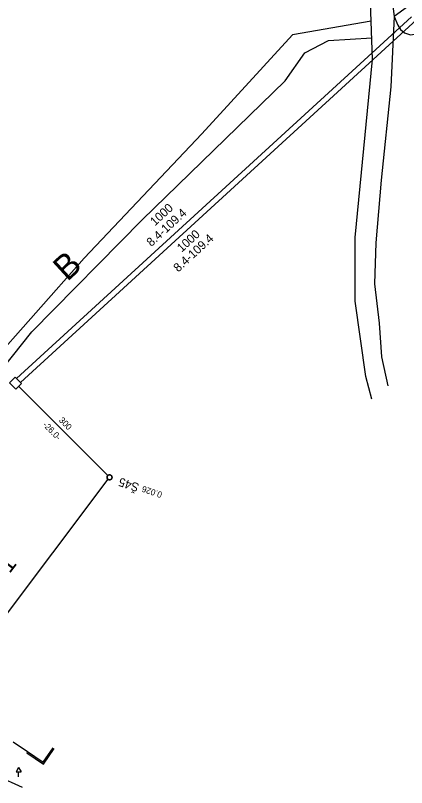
# Model space of a CAD drawing. Extents: x -574526 to -573537, y -1188297 to -1187280.
# Drawn here: x -573818.5 to -573739.4, y -1187727.9 to -1187571.7 of the extents above; entities that cross this region are included whole.
import ezdxf

# ---------------------------------------------------------------- set-up
doc = ezdxf.new("R2010")
doc.units = 0
for name, color, linetype in [('Vrstva 10', 7, 'Continuous'), ('Vrstva 13', 7, 'Continuous'), ('Vrstva 14', 7, 'Continuous'), ('Vrstva 18', 7, 'Continuous'), ('Vrstva 2', 7, 'Continuous'), ('Vrstva 20', 7, 'Continuous'), ('Vrstva 6', 7, 'Continuous'), ('Vrstva 8', 7, 'Continuous'), ('Vrstva 9', 7, 'Continuous')]:
    doc.layers.add(name, color=color, linetype=linetype)

# ---------------------------------------------------------------- blocks, each defined once
blk = doc.blocks.new('5$271')
at = {"layer": 'Vrstva 6'}
for p, q in [((0, 3.732), (-1, 2)), ((0, 3.732), (1, 2)), ((-1, 2), (1, 2)), ((0, 0), (0, 2))]:
    blk.add_line(p, q, dxfattribs=at)

msp = doc.modelspace()

# ---------------------------------------------------------------- linework, layer by layer
at = {"layer": 'Vrstva 10'}
msp.add_lwpolyline([(-573620.8, -1187483.84), (-573741.93, -1187571.94), (-573741.22, -1187573.73), (-573740.64, -1187574.56), (-573739.89, -1187575.23), (-573738.64, -1187575.65), (-573736.64, -1187575.31), (-573616.81, -1187489)], dxfattribs=at)
at = {"layer": 'Vrstva 2'}
for p, q in [((-573818.29, -1187645.17), (-573738.43, -1187572)), ((-573817.49, -1187645.96), (-573737.37, -1187572.55)), ((-573799.82, -1187664.79), (-573817.83, -1187646.74)), ((-573844.19, -1187724.63), (-573799.77, -1187665.54))]:
    msp.add_line(p, q, dxfattribs=at)
at = {"layer": 'Vrstva 20'}
for points in [[(-573795.53, -1187405.69), (-573792.23, -1187408.34), (-573784.28, -1187417.75), (-573780.7, -1187424.87), (-573775.33, -1187439.65), (-573771.1, -1187451.06), (-573764.6, -1187463.55), (-573752.36, -1187503.61), (-573747.53, -1187527.64), (-573741.93, -1187571.94), (-573742.6, -1187586.18), (-573744.6, -1187605.04), (-573745.68, -1187617.7), (-573745.93, -1187626.03), (-573745.01, -1187633.94), (-573744.51, -1187640.77), (-573743.23, -1187646.67)], [(-573746.49, -1187649.33), (-573747.68, -1187644.77), (-573749.84, -1187629.53), (-573749.84, -1187616.62), (-573746.34, -1187580.64), (-573746.59, -1187572.9), (-573747.09, -1187559.66), (-573752.76, -1187522.68), (-573756.77, -1187503.15), (-573764.52, -1187475.21), (-573771.52, -1187459.72), (-573776.68, -1187449.39), (-573786.08, -1187424.04)], [(-573746.59, -1187572.9), (-573762.51, -1187575.67), (-573780.83, -1187595.65), (-573804.57, -1187620.85), (-573824.18, -1187642.92)], [(-573838.44, -1187664.92), (-573815.18, -1187635.73), (-573792.91, -1187613.04), (-573763.97, -1187584.93), (-573760.01, -1187579.31), (-573755.22, -1187576.81), (-573746.49, -1187576.26)]]:
    msp.add_lwpolyline(points, dxfattribs=at)
at = {"layer": 'Vrstva 6'}
for p, q in [((-573818.98, -1187718.61), (-573816.03, -1187720.57)), ((-573816.03, -1187720.57), (-573816.2, -1187720.82)), ((-573816.2, -1187720.82), (-573812.81, -1187723.14)), ((-573816.03, -1187720.57), (-573812.89, -1187722.72)), ((-573812.89, -1187722.72), (-573810.9, -1187719.82)), ((-573812.81, -1187723.14), (-573810.65, -1187719.99))]:
    msp.add_line(p, q, dxfattribs=at)
at = {"layer": 'Vrstva 8'}
for points in [[(-573819.7, -1187646.02), (-573818.4, -1187647.31), (-573817.27, -1187646.17), (-573818.58, -1187644.88), (-573819.7, -1187646.02)], [(-573799.95, -1187665.02), (-573799.96, -1187665.07), (-573799.97, -1187665.12), (-573799.97, -1187665.17), (-573799.96, -1187665.23), (-573799.95, -1187665.28), (-573799.93, -1187665.33), (-573799.91, -1187665.37), (-573799.88, -1187665.42), (-573799.85, -1187665.46), (-573799.82, -1187665.5), (-573799.78, -1187665.53), (-573799.73, -1187665.56), (-573799.69, -1187665.59), (-573799.64, -1187665.61), (-573799.59, -1187665.63), (-573799.54, -1187665.64), (-573799.49, -1187665.64), (-573799.43, -1187665.64), (-573799.38, -1187665.64), (-573799.33, -1187665.62), (-573799.28, -1187665.61), (-573799.23, -1187665.58), (-573799.19, -1187665.56), (-573799.15, -1187665.53), (-573799.11, -1187665.49), (-573799.07, -1187665.45), (-573799.04, -1187665.41), (-573799.02, -1187665.36), (-573799, -1187665.32), (-573798.98, -1187665.27), (-573798.97, -1187665.21), (-573798.97, -1187665.16), (-573798.97, -1187665.11), (-573798.97, -1187665.06), (-573798.98, -1187665.01), (-573799, -1187664.96), (-573799.02, -1187664.91), (-573799.05, -1187664.86), (-573799.08, -1187664.82), (-573799.12, -1187664.78), (-573799.16, -1187664.75), (-573799.2, -1187664.72), (-573799.24, -1187664.69), (-573799.29, -1187664.67), (-573799.34, -1187664.66), (-573799.39, -1187664.65), (-573799.45, -1187664.64), (-573799.5, -1187664.64), (-573799.55, -1187664.65), (-573799.6, -1187664.66), (-573799.65, -1187664.68), (-573799.7, -1187664.7), (-573799.74, -1187664.73), (-573799.79, -1187664.76), (-573799.82, -1187664.79), (-573799.86, -1187664.83), (-573799.89, -1187664.87), (-573799.91, -1187664.92), (-573799.94, -1187664.97), (-573799.95, -1187665.02)]]:
    msp.add_lwpolyline(points, close=True, dxfattribs=at)
msp.add_circle((-573799.47, -1187665.14), 0.5, dxfattribs=at)
at = {"layer": 'Vrstva 9'}
msp.add_line((-573817.1, -1187727.87), (-573839.75, -1187717.56), dxfattribs=at)

# ---------------------------------------------------------------- block references
at = {"layer": 'Vrstva 6', "xscale": 0.5, "yscale": 0.5}
msp.add_blockref('5$271', (-573817.86, -1187725.69), dxfattribs=at)

# ---------------------------------------------------------------- texts
at = {"layer": 'Vrstva 13'}
msp.add_text('0.026', height=1.25, rotation=161.4832, dxfattribs=at).set_placement((-573788.72, -1187668.16))
at = {"layer": 'Vrstva 14'}
for s, height, rotation, p in [('1000', 1.75, 42.4969, (-573790.31, -1187614.4)), ('8.4-109.4', 1.75, 42.4969, (-573791.03, -1187618.58)), ('8.4-109.4', 1.75, 42.4969, (-573785.59, -1187623.74)), ('1000', 1.75, 42.4969, (-573784.88, -1187619.72)), ('B', 5, 42.4969, (-573808.02, -1187625.67)), ('300', 1.25, 314.389, (-573809.8, -1187653.7)), ('-26.0-', 1.25, 314.389, (-573813.06, -1187654.61)), ('B1', 3.499, 52.6574, (-573821.57, -1187687.2))]:
    msp.add_text(s, height=height, rotation=rotation, dxfattribs=at).set_placement(p)
at = {"layer": 'Vrstva 18'}
msp.add_text('Š45', height=1.75, rotation=161.4832, dxfattribs=at).set_placement((-573793.33, -1187666.48))

doc.saveas('drawing.dxf')
